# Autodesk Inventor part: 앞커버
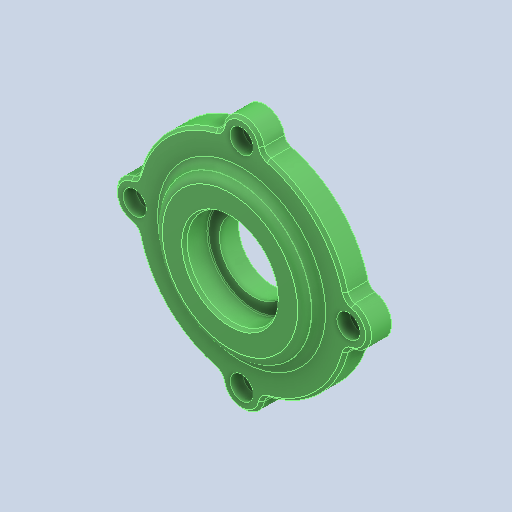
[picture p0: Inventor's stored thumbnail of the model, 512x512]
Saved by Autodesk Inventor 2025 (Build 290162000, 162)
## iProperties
Created: 2024-08
Part Number: 앞커버
Material: 알루미늄 6061
Document SubType Name: Modeling
Designer: SAMSUNG
Density: 2.71 g/cm^3
Appearance: 기본값
Company: 한국ATC센터
Author: jhkim
Sending System: Autodesk Inventor 2025
Preprocessor: ST-DEVELOPER v20
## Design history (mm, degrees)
feature "솔리드1"
node "솔리드2"
